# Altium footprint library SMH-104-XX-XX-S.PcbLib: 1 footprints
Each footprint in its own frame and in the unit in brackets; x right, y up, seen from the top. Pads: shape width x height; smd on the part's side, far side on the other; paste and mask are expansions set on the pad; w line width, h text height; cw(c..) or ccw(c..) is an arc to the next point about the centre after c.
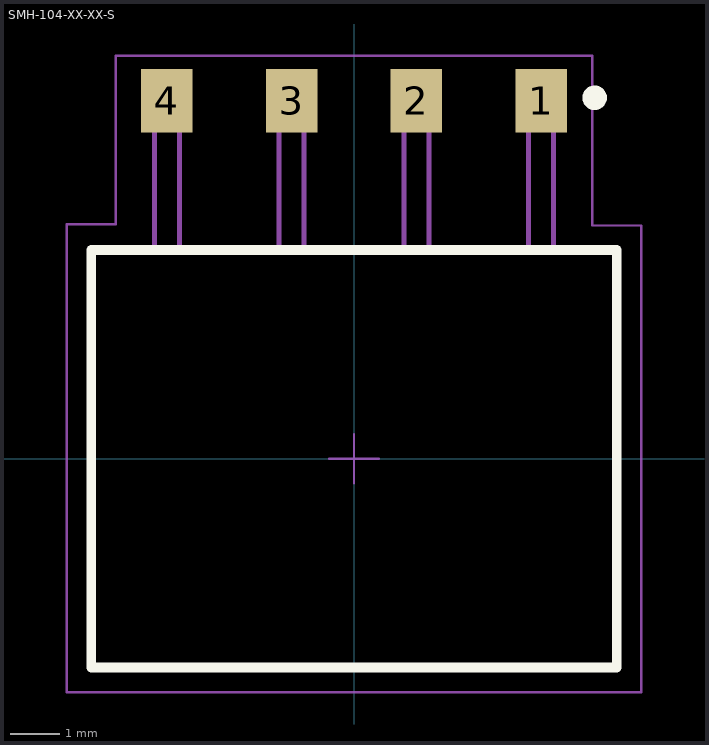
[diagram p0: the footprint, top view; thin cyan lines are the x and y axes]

## SMH-104-XX-XX-S [mm] "2.54mm pitch, socket assembly; horizontal, single row, SMT"
height 4.95
pads (4):
  rect 1.05x1.3 smd mask+0: 1(3.81,7.29) 2(1.27,7.29) 3(-1.27,7.29) 4(-3.81,7.29)
Top Overlay:
  circle w0.25: c4.9,7.35 r0.125
  lines w0.2: -5.35,-4.25 5.35,-4.25 5.35,4.25 -5.35,4.25 -5.35,-4.25
Mechanical 12:
  lines w0.001: -5.35,-4.25 5.35,-4.25 5.35,4.25 -5.35,4.25 -5.35,-4.25
Mechanical 13:
  lines w0.1: -4.064,4.267 -4.064,7.62 -3.556,7.62 -3.556,4.267 ; -1.524,4.267 -1.524,7.62 -1.016,7.62 -1.016,4.267 ; 1.016,4.267 1.016,7.62 1.524,7.62 1.524,4.267 ; 3.556,4.267 3.556,7.62 4.064,7.62 4.064,4.267 ; -5.35,-4.25 5.35,-4.25 5.35,4.25 -5.35,4.25 -5.35,-4.25
  text ".Designator" at 0,-0.127 h1.52
Mechanical 15:
  lines w0.05: -0.5,0 0.5,0 ; 0,-0.5 0,0.5 ; -5.85,-4.75 5.85,-4.75 5.85,4.75 4.85,4.75 4.85,8.204 -4.85,8.204 -4.85,4.775 -5.85,4.775 -5.85,-4.75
